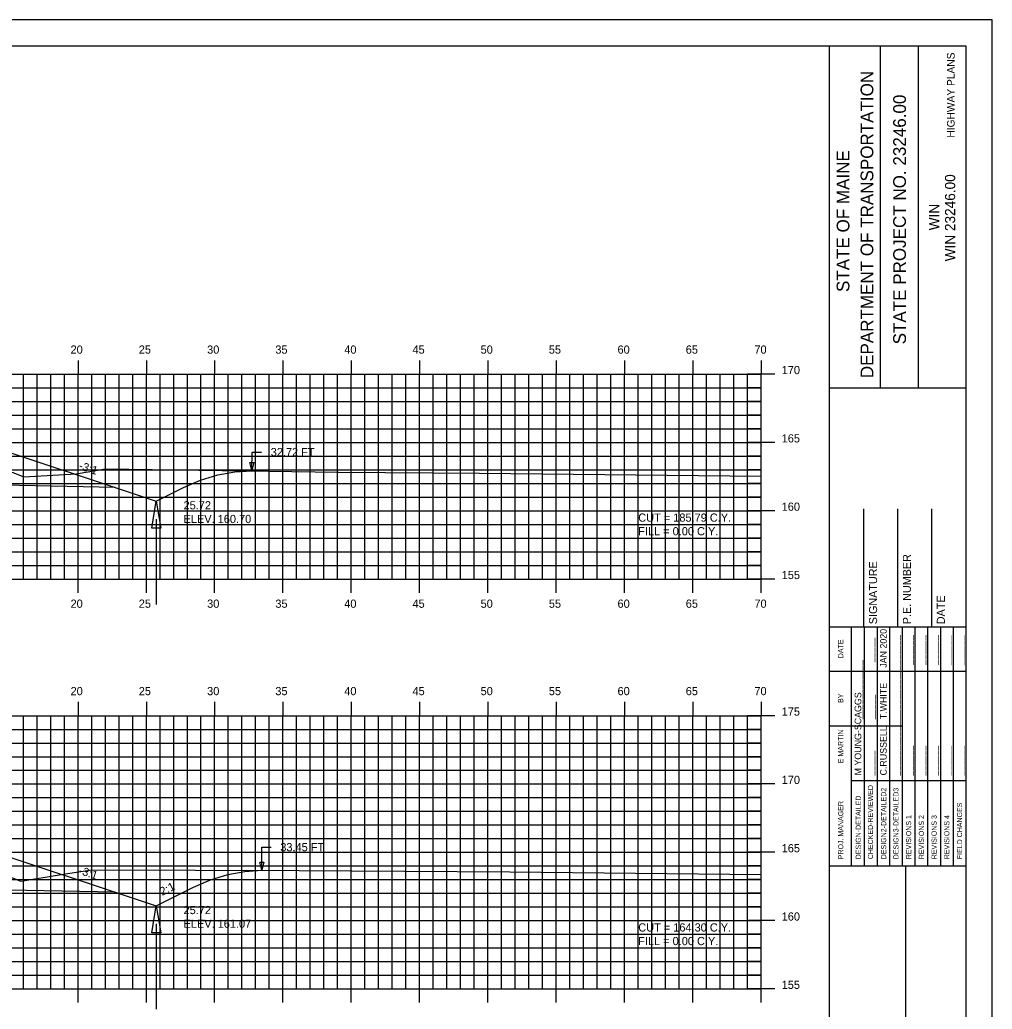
# Model space of a CAD drawing. Extents: x 1142755 to 1142925, y 608981 to 609091.
# Drawn here: x 1142853.5 to 1142924.7, y 609018.8 to 609091.3 of the extents above; entities that cross this region are included whole.
import ezdxf

# ---------------------------------------------------------------- set-up
doc = ezdxf.new("R2010")
doc.units = 0
for name, color, linetype in [('ANNOTATION', 7, 'Continuous'), ('BORDER', 7, 'Continuous'), ('D_Drainage_Ditch_Line', 7, 'Continuous'), ('D_Roadway_SlopeLines', 7, 'Continuous'), ('D_Roadway_SubGrade', 7, 'Continuous'), ('D_Text_Standard', 7, 'Continuous'), ('H_V ANNOTATION', 7, 'Continuous'), ('HIGHWAY_TITLE', 7, 'Continuous'), ('MAJOR', 7, 'Continuous'), ('MINOR', 7, 'Continuous'), ('PLOT BOUNDARY', 7, 'Continuous'), ('S_Roadway_Centerline', 7, 'Continuous')]:
    doc.layers.add(name, color=color, linetype=linetype)

msp = doc.modelspace()

# ---------------------------------------------------------------- linework, layer by layer
for points in [[(1142803.888, 609058.924), (1142805.138, 609058.829), (1142806.388, 609058.583), (1142807.638, 609058.185), (1142808.888, 609057.636), (1142812.085, 609056.037), (1142815.085, 609057.037), (1142822.809, 609059.612), (1142822.81, 609059.612), (1142826.81, 609059.772), (1142837.81, 609059.992), (1142848.81, 609059.772), (1142852.81, 609059.612), (1142860.533, 609057.037), (1142863.533, 609056.037), (1142865.53, 609057.036), (1142866.78, 609057.581), (1142868.03, 609057.965), (1142869.28, 609058.189), (1142870.53, 609058.252)], [(1142802.095, 609030.152), (1142803.345, 609030.075), (1142804.595, 609029.841), (1142805.845, 609029.451), (1142807.095, 609028.904), (1142812.085, 609026.409), (1142815.085, 609027.409), (1142822.809, 609029.983), (1142822.81, 609029.983), (1142826.81, 609030.143), (1142837.81, 609030.363), (1142848.81, 609030.143), (1142852.81, 609029.983), (1142860.533, 609027.409), (1142863.533, 609026.409), (1142866.262, 609027.773), (1142867.512, 609028.319), (1142868.762, 609028.709), (1142870.012, 609028.941), (1142871.262, 609029.016)]]:
    msp.add_lwpolyline(points)
at = {"layer": 'BORDER'}
for p, q in [((1142912.81, 608984.335), (1142912.81, 609089.335)), ((1142916.539, 609064.332), (1142916.539, 609089.332)), ((1142919.334, 609064.332), (1142919.334, 609089.332)), ((1142912.811, 609064.329), (1142922.81, 609064.329)), ((1142915.31, 609046.838), (1142915.31, 609055.485)), ((1142917.81, 609046.838), (1142917.81, 609055.485)), ((1142920.31, 609046.838), (1142920.31, 609055.485)), ((1142912.81, 609046.838), (1142922.81, 609046.838)), ((1142912.81, 609029.338), (1142922.81, 609029.338)), ((1142918.401, 608994.338), (1142918.401, 609029.338))]:
    msp.add_line(p, q, dxfattribs=at)
msp.add_lwpolyline([(1142762.81, 608984.335), (1142922.81, 608984.335), (1142922.81, 609089.335), (1142762.81, 609089.335)], close=True, dxfattribs=at)
for points in [[(1142914.425, 609043.588), (1142914.425, 609046.838)], [(1142915.358, 609029.341), (1142915.358, 609046.838)], [(1142916.289, 609046.838), (1142916.289, 609029.341)], [(1142917.221, 609029.341), (1142917.221, 609046.838)], [(1142918.153, 609029.341), (1142918.153, 609046.838)], [(1142919.084, 609029.341), (1142919.084, 609046.838)], [(1142920.016, 609029.341), (1142920.016, 609046.838)], [(1142920.948, 609029.341), (1142920.948, 609046.838)], [(1142921.879, 609029.341), (1142921.879, 609046.838)], [(1142914.426, 609029.341), (1142914.426, 609046.132)], [(1142912.81, 609043.588), (1142922.81, 609043.588)], [(1142912.81, 609039.588), (1142914.426, 609039.588)], [(1142914.425, 609039.588), (1142918.152, 609039.588)], [(1142914.425, 609035.588), (1142922.81, 609035.588)]]:
    msp.add_lwpolyline(points, dxfattribs=at)
at = {"layer": 'D_Drainage_Ditch_Line'}
for p, q in [((1142863.534, 609054.725), (1142863.533, 609048.482)), ((1142863.534, 609025.097), (1142863.533, 609018.853))]:
    msp.add_line(p, q, dxfattribs=at)
for points in [[(1142863.862, 609054.069), (1142863.205, 609054.069), (1142863.533, 609056.037)], [(1142863.862, 609024.44), (1142863.205, 609024.44), (1142863.533, 609026.409)]]:
    msp.add_lwpolyline(points, close=True, dxfattribs=at)
at = {"layer": 'D_Roadway_SlopeLines'}
for points in [[(1142863.533, 609056.037), (1142865.53, 609057.036), (1142866.78, 609057.581), (1142868.03, 609057.965), (1142869.28, 609058.189), (1142870.53, 609058.252)], [(1142860.533, 609057.037), (1142863.533, 609056.037)], [(1142863.533, 609026.409), (1142866.262, 609027.773), (1142867.512, 609028.319), (1142868.762, 609028.709), (1142870.012, 609028.941), (1142871.262, 609029.016)], [(1142860.533, 609027.409), (1142863.533, 609026.409)]]:
    msp.add_lwpolyline(points, dxfattribs=at)
at = {"layer": 'D_Roadway_SubGrade'}
for points in [[(1142848.81, 609059.355), (1142848.81, 609059.522), (1142852.81, 609059.362), (1142852.81, 609059.612), (1142852.81, 609059.612), (1142860.533, 609057.037), (1142848.81, 609057.272)], [(1142848.81, 609029.727), (1142848.81, 609029.893), (1142852.81, 609029.733), (1142852.81, 609029.983), (1142852.81, 609029.983), (1142860.533, 609027.409), (1142848.81, 609027.643)]]:
    msp.add_lwpolyline(points, close=True, dxfattribs=at)
at = {"layer": 'D_Text_Standard'}
for points in [[(1142870.53, 609058.286), (1142870.554, 609059.634), (1142871.234, 609059.634)], [(1142871.262, 609029.023), (1142871.254, 609030.71), (1142871.934, 609030.71)]]:
    msp.add_lwpolyline(points, dxfattribs=at)
for points in [[(1142870.53, 609058.286), (1142870.395, 609058.87), (1142870.686, 609058.865)], [(1142871.262, 609029.023), (1142871.114, 609029.604), (1142871.405, 609029.606)]]:
    msp.add_lwpolyline(points, close=True, dxfattribs=at)
at = {"layer": 'MAJOR'}
for p, q in [((1142857.81, 609066.337), (1142857.81, 609065.335)), ((1142862.81, 609066.337), (1142862.81, 609065.335)), ((1142867.81, 609066.337), (1142867.81, 609065.335)), ((1142872.81, 609066.337), (1142872.81, 609065.335)), ((1142877.81, 609066.337), (1142877.81, 609065.335)), ((1142882.81, 609066.337), (1142882.81, 609065.335)), ((1142887.81, 609066.337), (1142887.81, 609065.335)), ((1142892.81, 609066.337), (1142892.81, 609065.335)), ((1142897.81, 609066.337), (1142897.81, 609065.335)), ((1142902.81, 609066.337), (1142902.81, 609065.335)), ((1142907.81, 609066.337), (1142907.81, 609065.335)), ((1142767.81, 609065.335), (1142907.81, 609065.335)), ((1142767.81, 609065.335), (1142907.81, 609065.335)), ((1142857.81, 609050.335), (1142857.81, 609065.335)), ((1142862.81, 609050.335), (1142862.81, 609065.335)), ((1142867.81, 609050.335), (1142867.81, 609065.335)), ((1142872.81, 609050.335), (1142872.81, 609065.335)), ((1142877.81, 609050.335), (1142877.81, 609065.335)), ((1142882.81, 609050.335), (1142882.81, 609065.335)), ((1142887.81, 609050.335), (1142887.81, 609065.335)), ((1142892.81, 609050.335), (1142892.81, 609065.335)), ((1142897.81, 609050.335), (1142897.81, 609065.335)), ((1142902.81, 609050.335), (1142902.81, 609065.335)), ((1142908.812, 609065.335), (1142906.808, 609065.335)), ((1142907.81, 609050.335), (1142907.81, 609065.335)), ((1142907.81, 609050.335), (1142907.81, 609065.335)), ((1142767.81, 609060.335), (1142907.81, 609060.335)), ((1142908.812, 609060.335), (1142906.808, 609060.335)), ((1142767.81, 609055.335), (1142907.81, 609055.335)), ((1142908.812, 609055.335), (1142906.808, 609055.335)), ((1142767.81, 609050.335), (1142907.81, 609050.335)), ((1142767.81, 609050.335), (1142907.81, 609050.335)), ((1142857.81, 609049.333), (1142857.81, 609050.335)), ((1142862.81, 609049.333), (1142862.81, 609050.335)), ((1142867.81, 609049.333), (1142867.81, 609050.335)), ((1142872.81, 609049.333), (1142872.81, 609050.335)), ((1142877.81, 609049.333), (1142877.81, 609050.335)), ((1142882.81, 609049.333), (1142882.81, 609050.335)), ((1142887.81, 609049.333), (1142887.81, 609050.335)), ((1142892.81, 609049.333), (1142892.81, 609050.335)), ((1142897.81, 609049.333), (1142897.81, 609050.335)), ((1142902.81, 609049.333), (1142902.81, 609050.335)), ((1142908.812, 609050.335), (1142906.808, 609050.335)), ((1142907.81, 609049.333), (1142907.81, 609050.335)), ((1142857.81, 609041.337), (1142857.81, 609040.335)), ((1142862.81, 609041.337), (1142862.81, 609040.335)), ((1142867.81, 609041.337), (1142867.81, 609040.335)), ((1142872.81, 609041.337), (1142872.81, 609040.335)), ((1142877.81, 609041.337), (1142877.81, 609040.335)), ((1142882.81, 609041.337), (1142882.81, 609040.335)), ((1142887.81, 609041.337), (1142887.81, 609040.335)), ((1142892.81, 609041.337), (1142892.81, 609040.335)), ((1142897.81, 609041.337), (1142897.81, 609040.335)), ((1142902.81, 609041.337), (1142902.81, 609040.335)), ((1142907.81, 609041.337), (1142907.81, 609040.335)), ((1142767.81, 609040.335), (1142907.81, 609040.335)), ((1142767.81, 609040.335), (1142907.81, 609040.335)), ((1142857.81, 609020.335), (1142857.81, 609040.335)), ((1142862.81, 609020.335), (1142862.81, 609040.335)), ((1142867.81, 609020.335), (1142867.81, 609040.335)), ((1142872.81, 609020.335), (1142872.81, 609040.335)), ((1142877.81, 609020.335), (1142877.81, 609040.335)), ((1142882.81, 609020.335), (1142882.81, 609040.335)), ((1142887.81, 609020.335), (1142887.81, 609040.335)), ((1142892.81, 609020.335), (1142892.81, 609040.335)), ((1142897.81, 609020.335), (1142897.81, 609040.335)), ((1142902.81, 609020.335), (1142902.81, 609040.335)), ((1142908.812, 609040.335), (1142906.808, 609040.335)), ((1142907.81, 609020.335), (1142907.81, 609040.335)), ((1142907.81, 609020.335), (1142907.81, 609040.335)), ((1142767.81, 609035.335), (1142907.81, 609035.335)), ((1142908.812, 609035.335), (1142906.808, 609035.335)), ((1142767.81, 609030.335), (1142907.81, 609030.335)), ((1142908.812, 609030.335), (1142906.808, 609030.335)), ((1142767.81, 609025.335), (1142907.81, 609025.335)), ((1142908.812, 609025.335), (1142906.808, 609025.335)), ((1142767.81, 609020.335), (1142907.81, 609020.335)), ((1142767.81, 609020.335), (1142907.81, 609020.335)), ((1142857.81, 609019.333), (1142857.81, 609020.335)), ((1142862.81, 609019.333), (1142862.81, 609020.335)), ((1142867.81, 609019.333), (1142867.81, 609020.335)), ((1142872.81, 609019.333), (1142872.81, 609020.335)), ((1142877.81, 609019.333), (1142877.81, 609020.335)), ((1142882.81, 609019.333), (1142882.81, 609020.335)), ((1142887.81, 609019.333), (1142887.81, 609020.335)), ((1142892.81, 609019.333), (1142892.81, 609020.335)), ((1142897.81, 609019.333), (1142897.81, 609020.335)), ((1142902.81, 609019.333), (1142902.81, 609020.335)), ((1142908.812, 609020.335), (1142906.808, 609020.335)), ((1142907.81, 609019.333), (1142907.81, 609020.335))]:
    msp.add_line(p, q, dxfattribs=at)
at = {"layer": 'MINOR'}
for p, q in [((1142853.81, 609050.335), (1142853.81, 609065.335)), ((1142854.81, 609050.335), (1142854.81, 609065.335)), ((1142855.81, 609050.335), (1142855.81, 609065.335)), ((1142856.81, 609050.335), (1142856.81, 609065.335)), ((1142858.81, 609050.335), (1142858.81, 609065.335)), ((1142859.81, 609050.335), (1142859.81, 609065.335)), ((1142860.81, 609050.335), (1142860.81, 609065.335)), ((1142861.81, 609050.335), (1142861.81, 609065.335)), ((1142863.81, 609050.335), (1142863.81, 609065.335)), ((1142864.81, 609050.335), (1142864.81, 609065.335)), ((1142865.81, 609050.335), (1142865.81, 609065.335)), ((1142866.81, 609050.335), (1142866.81, 609065.335)), ((1142868.81, 609050.335), (1142868.81, 609065.335)), ((1142869.81, 609050.335), (1142869.81, 609065.335)), ((1142870.81, 609050.335), (1142870.81, 609065.335)), ((1142871.81, 609050.335), (1142871.81, 609065.335)), ((1142873.81, 609050.335), (1142873.81, 609065.335)), ((1142874.81, 609050.335), (1142874.81, 609065.335)), ((1142875.81, 609050.335), (1142875.81, 609065.335)), ((1142876.81, 609050.335), (1142876.81, 609065.335)), ((1142878.81, 609050.335), (1142878.81, 609065.335)), ((1142879.81, 609050.335), (1142879.81, 609065.335)), ((1142880.81, 609050.335), (1142880.81, 609065.335)), ((1142881.81, 609050.335), (1142881.81, 609065.335)), ((1142883.81, 609050.335), (1142883.81, 609065.335)), ((1142884.81, 609050.335), (1142884.81, 609065.335)), ((1142885.81, 609050.335), (1142885.81, 609065.335)), ((1142886.81, 609050.335), (1142886.81, 609065.335)), ((1142888.81, 609050.335), (1142888.81, 609065.335)), ((1142889.81, 609050.335), (1142889.81, 609065.335)), ((1142890.81, 609050.335), (1142890.81, 609065.335)), ((1142891.81, 609050.335), (1142891.81, 609065.335)), ((1142893.81, 609050.335), (1142893.81, 609065.335)), ((1142894.81, 609050.335), (1142894.81, 609065.335)), ((1142895.81, 609050.335), (1142895.81, 609065.335)), ((1142896.81, 609050.335), (1142896.81, 609065.335)), ((1142898.81, 609050.335), (1142898.81, 609065.335)), ((1142899.81, 609050.335), (1142899.81, 609065.335)), ((1142900.81, 609050.335), (1142900.81, 609065.335)), ((1142901.81, 609050.335), (1142901.81, 609065.335)), ((1142903.81, 609050.335), (1142903.81, 609065.335)), ((1142904.81, 609050.335), (1142904.81, 609065.335)), ((1142905.81, 609050.335), (1142905.81, 609065.335)), ((1142906.81, 609050.335), (1142906.81, 609065.335)), ((1142767.81, 609064.335), (1142907.81, 609064.335)), ((1142907.81, 609064.335), (1142906.808, 609064.335)), ((1142767.81, 609063.335), (1142907.81, 609063.335)), ((1142907.81, 609063.335), (1142906.808, 609063.335)), ((1142767.81, 609062.335), (1142907.81, 609062.335)), ((1142907.81, 609062.335), (1142906.808, 609062.335)), ((1142767.81, 609061.335), (1142907.81, 609061.335)), ((1142907.81, 609061.335), (1142906.808, 609061.335)), ((1142767.81, 609059.335), (1142907.81, 609059.335)), ((1142907.81, 609059.335), (1142906.808, 609059.335)), ((1142767.81, 609058.335), (1142907.81, 609058.335)), ((1142907.81, 609058.335), (1142906.808, 609058.335)), ((1142767.81, 609057.335), (1142907.81, 609057.335)), ((1142907.81, 609057.335), (1142906.808, 609057.335)), ((1142767.81, 609056.335), (1142907.81, 609056.335)), ((1142907.81, 609056.335), (1142906.808, 609056.335)), ((1142767.81, 609054.335), (1142907.81, 609054.335)), ((1142907.81, 609054.335), (1142906.808, 609054.335)), ((1142767.81, 609053.335), (1142907.81, 609053.335)), ((1142907.81, 609053.335), (1142906.808, 609053.335)), ((1142767.81, 609052.335), (1142907.81, 609052.335)), ((1142907.81, 609052.335), (1142906.808, 609052.335)), ((1142767.81, 609051.335), (1142907.81, 609051.335)), ((1142907.81, 609051.335), (1142906.808, 609051.335)), ((1142853.81, 609020.335), (1142853.81, 609040.335)), ((1142854.81, 609020.335), (1142854.81, 609040.335)), ((1142855.81, 609020.335), (1142855.81, 609040.335)), ((1142856.81, 609020.335), (1142856.81, 609040.335)), ((1142858.81, 609020.335), (1142858.81, 609040.335)), ((1142859.81, 609020.335), (1142859.81, 609040.335)), ((1142860.81, 609020.335), (1142860.81, 609040.335)), ((1142861.81, 609020.335), (1142861.81, 609040.335)), ((1142863.81, 609020.335), (1142863.81, 609040.335)), ((1142864.81, 609020.335), (1142864.81, 609040.335)), ((1142865.81, 609020.335), (1142865.81, 609040.335)), ((1142866.81, 609020.335), (1142866.81, 609040.335)), ((1142868.81, 609020.335), (1142868.81, 609040.335)), ((1142869.81, 609020.335), (1142869.81, 609040.335)), ((1142870.81, 609020.335), (1142870.81, 609040.335)), ((1142871.81, 609020.335), (1142871.81, 609040.335)), ((1142873.81, 609020.335), (1142873.81, 609040.335)), ((1142874.81, 609020.335), (1142874.81, 609040.335)), ((1142875.81, 609020.335), (1142875.81, 609040.335)), ((1142876.81, 609020.335), (1142876.81, 609040.335)), ((1142878.81, 609020.335), (1142878.81, 609040.335)), ((1142879.81, 609020.335), (1142879.81, 609040.335)), ((1142880.81, 609020.335), (1142880.81, 609040.335)), ((1142881.81, 609020.335), (1142881.81, 609040.335)), ((1142883.81, 609020.335), (1142883.81, 609040.335)), ((1142884.81, 609020.335), (1142884.81, 609040.335)), ((1142885.81, 609020.335), (1142885.81, 609040.335)), ((1142886.81, 609020.335), (1142886.81, 609040.335)), ((1142888.81, 609020.335), (1142888.81, 609040.335)), ((1142889.81, 609020.335), (1142889.81, 609040.335)), ((1142890.81, 609020.335), (1142890.81, 609040.335)), ((1142891.81, 609020.335), (1142891.81, 609040.335)), ((1142893.81, 609020.335), (1142893.81, 609040.335)), ((1142894.81, 609020.335), (1142894.81, 609040.335)), ((1142895.81, 609020.335), (1142895.81, 609040.335)), ((1142896.81, 609020.335), (1142896.81, 609040.335)), ((1142898.81, 609020.335), (1142898.81, 609040.335)), ((1142899.81, 609020.335), (1142899.81, 609040.335)), ((1142900.81, 609020.335), (1142900.81, 609040.335)), ((1142901.81, 609020.335), (1142901.81, 609040.335)), ((1142903.81, 609020.335), (1142903.81, 609040.335)), ((1142904.81, 609020.335), (1142904.81, 609040.335)), ((1142905.81, 609020.335), (1142905.81, 609040.335)), ((1142906.81, 609020.335), (1142906.81, 609040.335)), ((1142767.81, 609039.335), (1142907.81, 609039.335)), ((1142907.81, 609039.335), (1142906.808, 609039.335)), ((1142767.81, 609038.335), (1142907.81, 609038.335)), ((1142907.81, 609038.335), (1142906.808, 609038.335)), ((1142767.81, 609037.335), (1142907.81, 609037.335)), ((1142907.81, 609037.335), (1142906.808, 609037.335)), ((1142767.81, 609036.335), (1142907.81, 609036.335)), ((1142907.81, 609036.335), (1142906.808, 609036.335)), ((1142767.81, 609034.335), (1142907.81, 609034.335)), ((1142907.81, 609034.335), (1142906.808, 609034.335)), ((1142767.81, 609033.335), (1142907.81, 609033.335)), ((1142907.81, 609033.335), (1142906.808, 609033.335)), ((1142767.81, 609032.335), (1142907.81, 609032.335)), ((1142907.81, 609032.335), (1142906.808, 609032.335)), ((1142767.81, 609031.335), (1142907.81, 609031.335)), ((1142907.81, 609031.335), (1142906.808, 609031.335)), ((1142767.81, 609029.335), (1142907.81, 609029.335)), ((1142907.81, 609029.335), (1142906.808, 609029.335)), ((1142767.81, 609028.335), (1142907.81, 609028.335)), ((1142907.81, 609028.335), (1142906.808, 609028.335)), ((1142767.81, 609027.335), (1142907.81, 609027.335)), ((1142907.81, 609027.335), (1142906.808, 609027.335)), ((1142767.81, 609026.335), (1142907.81, 609026.335)), ((1142907.81, 609026.335), (1142906.808, 609026.335)), ((1142767.81, 609024.335), (1142907.81, 609024.335)), ((1142907.81, 609024.335), (1142906.808, 609024.335)), ((1142767.81, 609023.335), (1142907.81, 609023.335)), ((1142907.81, 609023.335), (1142906.808, 609023.335)), ((1142767.81, 609022.335), (1142907.81, 609022.335)), ((1142907.81, 609022.335), (1142906.808, 609022.335)), ((1142767.81, 609021.335), (1142907.81, 609021.335)), ((1142907.81, 609021.335), (1142906.808, 609021.335))]:
    msp.add_line(p, q, dxfattribs=at)
at = {"layer": 'PLOT BOUNDARY'}
msp.add_lwpolyline([(1142754.717, 608981.276), (1142924.717, 608981.276), (1142924.717, 609091.276), (1142754.717, 609091.276)], close=True, dxfattribs=at)
at = {"layer": 'S_Roadway_Centerline'}
for points in [[(1142767.81, 609058.735), (1142789.999, 609058.859), (1142798.177, 609059.01), (1142813.177, 609058.784), (1142815.825, 609058.433), (1142818.214, 609057.737), (1142819.359, 609058.049), (1142821.097, 609058.497), (1142823.175, 609058.691), (1142824.483, 609058.817), (1142829.243, 609058.936), (1142836.068, 609059.165), (1142842.737, 609059.067), (1142847.022, 609058.992), (1142848.858, 609058.805), (1142851.167, 609058.627), (1142853.046, 609058.141), (1142853.844, 609057.819), (1142857.677, 609058.043), (1142859.813, 609058.396), (1142876.869, 609058.167), (1142887.187, 609058.09), (1142907.81, 609057.874)], [(1142852.506, 609028.667), (1142853.62, 609028.219), (1142856.578, 609028.713), (1142858.816, 609029.052), (1142874.002, 609029.008), (1142889.42, 609028.9), (1142907.81, 609028.704)]]:
    msp.add_lwpolyline(points, dxfattribs=at)

# ---------------------------------------------------------------- texts
at = {"layer": 'ANNOTATION'}
for s, rotation, p in [('-3:1', 341.56521, (1142857.821, 609058.396)), ('-3:1', 341.56521, (1142857.821, 609028.767)), ('2:1', 26.56505, (1142863.97, 609027.145))]:
    msp.add_text(s, height=0.6, rotation=rotation, dxfattribs=at).set_placement(p)
at = {"layer": 'BORDER'}
for s, height, p in [('DEPARTMENT OF TRANSPORTATION', 0.93176, (1142916.017, 609065.041)), ('STATE PROJECT NO. 23246.00', 0.93176, (1142918.402, 609067.517)), ('STATE OF MAINE', 0.93176, (1142914.265, 609071.347)), ('WIN 23246.00', 0.74527, (1142922.006, 609073.596)), ('WIN', 0.7453, (1142920.847, 609075.865)), ('SIGNATURE', 0.5906, (1142916.291, 609047.03)), ('P.E. NUMBER', 0.59055, (1142918.771, 609047.03)), ('DATE', 0.5906, (1142921.251, 609047.03)), ('JAN 2020', 0.4845, (1142916.996, 609043.843)), ('DATE', 0.3714, (1142913.814, 609044.544)), ('_____', 0.4845, (1142916.028, 609044.243)), ('______', 0.4845, (1142917.891, 609044.063)), ('______', 0.4845, (1142918.823, 609044.065)), ('______', 0.4845, (1142919.754, 609044.067)), ('______', 0.4845, (1142920.686, 609044.067)), ('______', 0.4845, (1142921.618, 609044.036)), ('______', 0.4845, (1142922.549, 609044.036)), ('____________', 0.48455, (1142915.133, 609040.073)), ('____________', 0.48455, (1142917.891, 609040.073)), ('T.WHITE', 0.4845, (1142916.996, 609040.073)), ('BY', 0.3714, (1142913.814, 609041.273)), ('M YOUNG-SCAGGS', 0.48455, (1142915.133, 609035.961)), ('_____', 0.4845, (1142916.065, 609040.073)), ('____________', 0.48455, (1142917.891, 609035.961)), ('C.RUSSELL', 0.4845, (1142916.996, 609035.961)), ('E MARTIN', 0.3727, (1142913.814, 609036.855)), ('______', 0.4845, (1142918.823, 609035.961)), ('______', 0.4845, (1142919.754, 609035.961)), ('______', 0.4845, (1142920.686, 609035.961)), ('______', 0.4845, (1142921.618, 609035.961)), ('______', 0.4845, (1142922.549, 609035.961)), ('_____', 0.4845, (1142916.028, 609035.961)), ('CHECKED-REVIEWED', 0.37275, (1142915.991, 609029.826)), ('DESIGN-DETAILED', 0.37275, (1142915.097, 609029.826)), ('DESIGN2-DETAILED2', 0.37275, (1142916.96, 609029.826)), ('DESIGN3-DETAILED3', 0.37275, (1142917.855, 609029.826)), ('PROJ. MANAGER', 0.37275, (1142913.814, 609029.826)), ('FIELD CHANGES', 0.37275, (1142922.513, 609029.826)), ('REVISIONS 1', 0.37275, (1142918.786, 609029.826)), ('REVISIONS 2', 0.37275, (1142919.718, 609029.826)), ('REVISIONS 3', 0.37275, (1142920.65, 609029.826)), ('REVISIONS 4', 0.37275, (1142921.581, 609029.826))]:
    msp.add_text(s, height=height, rotation=90, dxfattribs=at).set_placement(p)
at = {"layer": 'D_Text_Standard'}
for s, p in [('32.72 FT', (1142871.914, 609059.334)), ('25.72', (1142865.534, 609055.437)), ('ELEV. 160.70', (1142865.534, 609054.435)), ('CUT = 185.79 C.Y.', (1142898.81, 609054.535)), ('FILL = 0.00 C.Y.', (1142898.81, 609053.539)), ('33.45 FT', (1142872.614, 609030.41)), ('25.72', (1142865.534, 609025.809)), ('ELEV. 161.07', (1142865.534, 609024.807)), ('CUT = 164.30 C.Y.', (1142898.81, 609024.535)), ('FILL = 0.00 C.Y.', (1142898.81, 609023.539))]:
    msp.add_text(s, height=0.6, dxfattribs=at).set_placement(p)
at = {"layer": 'H_V ANNOTATION'}
for s, p in [('20', (1142857.264, 609066.835)), ('25', (1142862.256, 609066.835)), ('30', (1142867.259, 609066.835)), ('35', (1142872.251, 609066.835)), ('40', (1142877.296, 609066.835)), ('45', (1142882.288, 609066.835)), ('50', (1142887.275, 609066.835)), ('55', (1142892.267, 609066.835)), ('60', (1142897.296, 609066.835)), ('65', (1142902.288, 609066.835)), ('70', (1142907.312, 609066.835)), ('170', (1142909.31, 609065.335)), ('165', (1142909.31, 609060.335)), ('160', (1142909.31, 609055.335)), ('155', (1142909.31, 609050.335)), ('20', (1142857.264, 609048.235)), ('25', (1142862.256, 609048.235)), ('30', (1142867.259, 609048.235)), ('35', (1142872.251, 609048.235)), ('40', (1142877.296, 609048.235)), ('45', (1142882.288, 609048.235)), ('50', (1142887.275, 609048.235)), ('55', (1142892.267, 609048.235)), ('60', (1142897.296, 609048.235)), ('65', (1142902.288, 609048.235)), ('70', (1142907.312, 609048.235)), ('20', (1142857.264, 609041.835)), ('25', (1142862.256, 609041.835)), ('30', (1142867.259, 609041.835)), ('35', (1142872.251, 609041.835)), ('40', (1142877.296, 609041.835)), ('45', (1142882.288, 609041.835)), ('50', (1142887.275, 609041.835)), ('55', (1142892.267, 609041.835)), ('60', (1142897.296, 609041.835)), ('65', (1142902.288, 609041.835)), ('70', (1142907.312, 609041.835)), ('175', (1142909.31, 609040.335)), ('170', (1142909.31, 609035.335)), ('165', (1142909.31, 609030.335)), ('160', (1142909.31, 609025.335)), ('155', (1142909.31, 609020.335))]:
    msp.add_text(s, height=0.6, dxfattribs=at).set_placement(p)
at = {"layer": 'HIGHWAY_TITLE'}
msp.add_text('HIGHWAY PLANS', height=0.55901, rotation=90, dxfattribs=at).set_placement((1142921.968, 609082.65))

doc.saveas('drawing.dxf')
